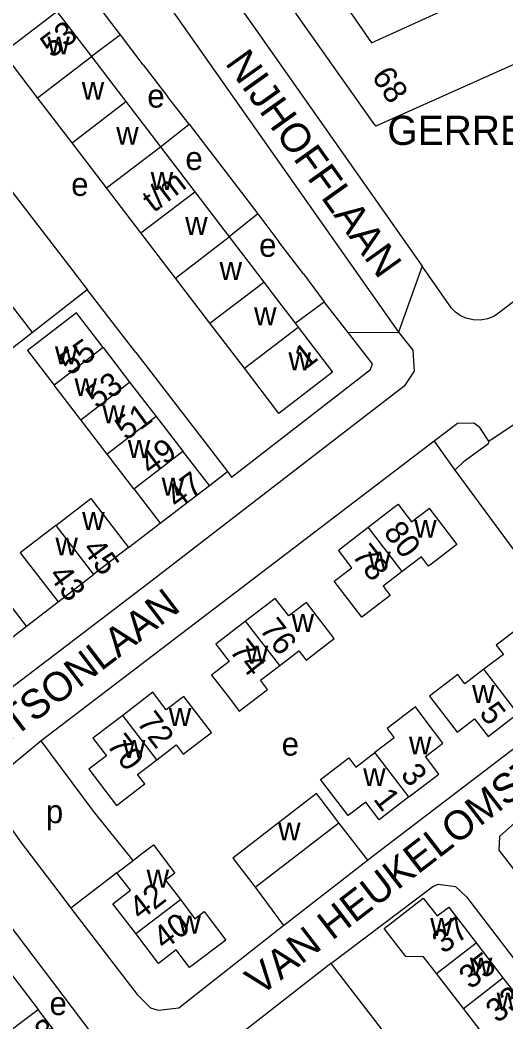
# Model space of a CAD drawing. Extents: x 158848 to 160613, y 385889 to 387762.
# Drawn here: x 160197.3 to 160280.6, y 386662.2 to 386833.8 of the extents above; entities that cross this region are included whole.
import ezdxf

# ---------------------------------------------------------------- set-up
doc = ezdxf.new("R2010")
doc.units = 0
for name, color, linetype in [('BLT_Basislijn', 7, 'Continuous'), ('BLT_Bebouwing', 7, 'Continuous'), ('BLT_Centroide', 7, 'Continuous'), ('BLT_Huisnummer', 7, 'Continuous'), ('BLT_Huisnummer_ tussenligend', 7, 'Continuous'), ('BLT_Huisnummer_reeks', 7, 'Continuous'), ('BLT_Onderverdeling_panden', 7, 'Continuous'), ('BLT_Straatnaam', 7, 'Continuous'), ('BLT_Vlakafsluiter', 7, 'Continuous')]:
    doc.layers.add(name, color=color, linetype=linetype)

msp = doc.modelspace()

# ---------------------------------------------------------------- linework, layer by layer
at = {"layer": 'BLT_Basislijn'}
for p, q in [((160214.52, 386831.26), (160210.62, 386836.33)), ((160214.52, 386831.26), (160209.53, 386827.53)), ((160218.39, 386826.08), (160214.52, 386831.26)), ((160218.39, 386826.08), (160222.58, 386820.68)), ((160226.29, 386815.94), (160222.58, 386820.68)), ((160221.34, 386812.08), (160226.29, 386815.94)), ((160226.29, 386815.94), (160238.04, 386800.58)), ((160238.04, 386800.58), (160233.15, 386796.63)), ((160238.04, 386800.58), (160241.64, 386795.77)), ((160245.86, 386790.28), (160241.64, 386795.77)), ((160245.86, 386790.28), (160249.43, 386785.51)), ((160199.36, 386780.27), (160208.81, 386787.6)), ((160217.12, 386776.82), (160208.81, 386787.6)), ((160195, 386785.9), (160199.36, 386780.27)), ((160244.45, 386781.85), (160249.43, 386785.51)), ((160253.56, 386780.23), (160249.43, 386785.51)), ((160188.56, 386771.9), (160199.36, 386780.27)), ((160268.26, 386761.65), (160200.94, 386710.29)), ((160268.26, 386761.65), (160271.82, 386756.68)), ((160229.74, 386754.03), (160232.84, 386756.43)), ((160271.82, 386756.68), (160294.41, 386725.95)), ((160215.91, 386743.44), (160221.3, 386747.61)), ((160198.42, 386729.93), (160203.82, 386734.15)), ((160256.88, 386689.9), (160251.95, 386696.29)), ((160188.23, 386688.31), (160218.11, 386648.95)), ((160213.91, 386687.72), (160206.02, 386681.65)), ((160237.59, 386685.24), (160242.45, 386678.66)), ((160191.71, 386675.65), (160200.38, 386664.32)), ((160250.58, 386672.17), (160304.3, 386602.61))]:
    msp.add_line(p, q, dxfattribs=at)
for points in [[(160222.17, 386854.05), (160237.27, 386832.78), (160266.19, 386791.63)], [(160209.22, 386848.6), (160210.11, 386849.02), (160211.97, 386849.29), (160213.28, 386848.98), (160214.47, 386848.13), (160262.15, 386780.3)], [(160179.24, 386825.93), (160205.57, 386791.81)], [(160290.48, 386794.11), (160288.29, 386791.23), (160286.43, 386789.22), (160284.64, 386787.62), (160279.32, 386783.55), (160278.5, 386783.02), (160277.43, 386782.58), (160276.23, 386782.36), (160274.94, 386782.4), (160273.73, 386782.71), (160272.75, 386783.14), (160271.94, 386783.74), (160271.25, 386784.44), (160266.19, 386791.63)], [(160205.57, 386791.81), (160208.81, 386787.6)], [(160262.15, 386780.3), (160264.62, 386777.22), (160264.84, 386773.63), (160263.16, 386771.08), (160219.2, 386737.19), (160136.62, 386674.36), (160133.98, 386672.88), (160132.87, 386672.77), (160131.28, 386673.09), (160129.35, 386675.17), (160128.56, 386676.18)], [(160232.84, 386756.43), (160233.56, 386755.48), (160257.38, 386773.93), (160257.68, 386774.9), (160253.56, 386780.23)], [(160253.56, 386780.23), (160262.15, 386780.3)], [(160217.12, 386776.82), (160232.84, 386756.43)], [(160277.67, 386761.63), (160276.11, 386763.97), (160275.1, 386764.74), (160272.26, 386764.66), (160268.26, 386761.65)], [(160271.82, 386756.68), (160273.49, 386758.29), (160277.58, 386761.27), (160277.67, 386761.63)], [(160297.47, 386721.3), (160287.96, 386713.58), (160256.88, 386689.9)], [(160319.16, 386701), (160310.98, 386712.3), (160308.27, 386714.83), (160305.15, 386714.7), (160285.31, 386699.15), (160279.48, 386693.93), (160279.36, 386691.57), (160288.87, 386679.32)], [(160200.94, 386710.29), (160193.73, 386704.4), (160192.73, 386702.17), (160192.97, 386699.26)], [(160216.66, 386689.84), (160209.88, 386698.25), (160200.94, 386710.29)], [(160192.97, 386699.26), (160197.35, 386693), (160204.67, 386683.42), (160206.02, 386681.65)], [(160242.45, 386678.66), (160256.58, 386689.67), (160256.88, 386689.9)], [(160250.58, 386672.17), (160268.02, 386685.39), (160268.98, 386685.74), (160271.92, 386685.34), (160273.79, 386683.57), (160325.19, 386616.52), (160325.69, 386615.85)], [(160206.02, 386681.65), (160217.34, 386666.87), (160219.66, 386664.61), (160220.94, 386664.18), (160224.53, 386664.56), (160241.5, 386677.92), (160242.45, 386678.66)], [(160250.58, 386672.17), (160230.2, 386656.33), (160228.95, 386654.25), (160229.21, 386651.93), (160280.78, 386584.48)]]:
    msp.add_lwpolyline(points, dxfattribs=at)
at = {"layer": 'BLT_Bebouwing'}
for p, q in [((160209.53, 386827.53), (160213.38, 386822.49)), ((160213.38, 386822.49), (160215.43, 386819.8)), ((160206.21, 386812.75), (160200.31, 386820.47)), ((160215.43, 386819.8), (160217.65, 386816.9)), ((160217.65, 386816.9), (160221.34, 386812.08)), ((160212.12, 386805.03), (160206.21, 386812.75)), ((160221.34, 386812.08), (160227.25, 386804.35)), ((160218.02, 386797.3), (160212.12, 386805.03)), ((160227.25, 386804.35), (160233.15, 386796.63)), ((160223.93, 386789.58), (160218.02, 386797.3)), ((160233.15, 386796.63), (160236.89, 386791.75)), ((160236.89, 386791.75), (160239.06, 386788.9)), ((160229.84, 386781.85), (160223.93, 386789.58)), ((160239.06, 386788.9), (160241.03, 386786.32)), ((160241.03, 386786.32), (160244.45, 386781.85)), ((160235.74, 386774.13), (160229.84, 386781.85)), ((160244.45, 386781.85), (160244.96, 386781.18)), ((160211.52, 386777.68), (160216.07, 386771.77)), ((160207.7, 386765.32), (160203.15, 386771.24)), ((160216.07, 386771.77), (160220.63, 386765.85)), ((160212.24, 386759.4), (160207.7, 386765.32)), ((160220.63, 386765.85), (160225.18, 386759.94)), ((160216.79, 386753.48), (160212.24, 386759.4)), ((160237.59, 386685.24), (160251.95, 386696.29)), ((160213.91, 386687.72), (160216.66, 386689.84)), ((160275.46, 386675.7), (160280.07, 386669.72)), ((160273.28, 386664.49), (160268.68, 386670.47)), ((160280.07, 386669.72), (160284.67, 386663.74)), ((160205.04, 386658.26), (160200.38, 386664.32)), ((160277.88, 386658.52), (160273.28, 386664.49))]:
    msp.add_line(p, q, dxfattribs=at)
msp.add_lwpolyline([(160244.56, 386848.67), (160257.55, 386829.86), (160300.86, 386849.59), (160291.65, 386861.46)], close=True, dxfattribs=at)
for points in [[(160309.97, 386840.55), (160298.85, 386835.59), (160301.29, 386833.31), (160286.63, 386826.7), (160285.77, 386827.9), (160258.27, 386815.6), (160257.37, 386816.84), (160238.05, 386844.21)], [(160200.31, 386820.47), (160194.4, 386828.2), (160203.62, 386835.25), (160209.53, 386827.53)], [(160211.52, 386777.68), (160206.97, 386783.6), (160198.59, 386777.17), (160203.15, 386771.24)], [(160244.96, 386781.18), (160250.87, 386773.45), (160241.65, 386766.4), (160235.74, 386774.13)], [(160229.74, 386754.03), (160225.18, 386759.94)], [(160216.79, 386753.48), (160221.3, 386747.61)], [(160221.3, 386747.61), (160229.74, 386754.03)], [(160203.42, 386747.18), (160209.45, 386751.81), (160215.91, 386743.44)], [(160256.98, 386746.94), (160260.95, 386750), (160262.08, 386750.87), (160262.74, 386750), (160264.4, 386747.83), (160267.25, 386750), (160267.44, 386750.15), (160267.55, 386750), (160272.17, 386743.97), (160268.2, 386740.93), (160267.32, 386740.26), (160266.11, 386741.85), (160262.81, 386739.33)], [(160203.42, 386747.18), (160197.34, 386742.52), (160203.82, 386734.15)], [(160262.81, 386739.33), (160259.52, 386736.8), (160260.73, 386735.22), (160255.89, 386731.51), (160254.19, 386733.71), (160251.13, 386737.67), (160254.16, 386739.96), (160251.86, 386742.99), (160256.98, 386746.94)], [(160215.91, 386743.44), (160209.87, 386738.79)], [(160203.82, 386734.15), (160209.87, 386738.79)], [(160198.42, 386729.93), (160193.87, 386735.85)], [(160241.8, 386723.21), (160245.09, 386725.73), (160246.31, 386724.15), (160251.14, 386727.85), (160249.43, 386730.07), (160246.38, 386734.03), (160243.36, 386731.73), (160241.04, 386734.72), (160235.96, 386730.83)], [(160235.96, 386730.83), (160230.83, 386726.9), (160233.16, 386723.9), (160230.13, 386721.59), (160233.17, 386717.62), (160234.87, 386715.4), (160239.71, 386719.1), (160238.5, 386720.69), (160241.8, 386723.21)], [(160190.05, 386723.48), (160198.42, 386729.93)], [(160282.64, 386714.98), (160287.75, 386718.89), (160285.49, 386721.89), (160288.47, 386724.22), (160283.76, 386730.41), (160279.79, 386727.38), (160278.91, 386726.71), (160280.13, 386725.12), (160276.81, 386722.59)], [(160276.81, 386722.59), (160273.53, 386720.09), (160272.32, 386721.68), (160267.47, 386717.98), (160269.16, 386715.76), (160272.19, 386711.78), (160275.21, 386714.08), (160277.52, 386711.06), (160282.64, 386714.98)], [(160220.74, 386707.07), (160224.04, 386709.61), (160225.26, 386708.02), (160230.11, 386711.74), (160228.4, 386713.96), (160225.36, 386717.93), (160222.35, 386715.62), (160220.04, 386718.63), (160214.89, 386714.68)], [(160263.95, 386700.7), (160269.06, 386704.6), (160266.77, 386707.61), (160269.77, 386709.93), (160266.74, 386713.91), (160265.05, 386716.12), (160260.21, 386712.42), (160261.42, 386710.84), (160258.13, 386708.32)], [(160214.89, 386714.68), (160209.79, 386710.77), (160212.1, 386707.77), (160209.1, 386705.45), (160213.83, 386699.23), (160217.79, 386702.28), (160218.67, 386702.95), (160217.45, 386704.54), (160220.74, 386707.07)], [(160253.54, 386697.51), (160250.49, 386701.48), (160248.79, 386703.7), (160253.63, 386707.4), (160254.84, 386705.81), (160258.13, 386708.32)], [(160251.95, 386696.29), (160248.9, 386700.25), (160248.11, 386701.28), (160233.75, 386690.24), (160234.54, 386689.21), (160237.59, 386685.24)], [(160263.95, 386700.7), (160258.85, 386696.8), (160256.55, 386699.8), (160253.54, 386697.51)], [(160216.66, 386689.84), (160217.88, 386690.77), (160220.15, 386692.52), (160223.84, 386687.67), (160222.25, 386686.46), (160224.77, 386683.15)], [(160217.12, 386677.3), (160213.21, 386682.41), (160216.22, 386684.71), (160213.91, 386687.72)], [(160224.77, 386683.15), (160227.28, 386679.85), (160228.87, 386681.06), (160229.54, 386680.18), (160232.56, 386676.2), (160226.36, 386671.48), (160224.06, 386674.49), (160221.04, 386672.19), (160217.12, 386677.3)], [(160268.68, 386670.47), (160266.47, 386673.33), (160263.44, 386673.35), (160259.7, 386678.18), (160266.39, 386683.37), (160268.79, 386680.32), (160270.77, 386681.8), (160275.46, 386675.7)], [(160198.22, 386653.02), (160193.56, 386659.08), (160196.97, 386661.7), (160200.38, 386664.32)]]:
    msp.add_lwpolyline(points, dxfattribs=at)
at = {"layer": 'BLT_Onderverdeling_panden'}
for p, q in [((160200.31, 386820.47), (160209.53, 386827.53)), ((160206.21, 386812.75), (160215.43, 386819.8)), ((160212.12, 386805.03), (160221.34, 386812.08)), ((160218.02, 386797.3), (160227.25, 386804.35)), ((160223.93, 386789.58), (160233.15, 386796.63)), ((160229.84, 386781.85), (160239.06, 386788.9)), ((160235.74, 386774.13), (160244.96, 386781.18)), ((160211.52, 386777.68), (160203.15, 386771.24)), ((160207.7, 386765.32), (160216.07, 386771.77)), ((160220.63, 386765.85), (160212.24, 386759.4)), ((160216.79, 386753.48), (160225.18, 386759.94)), ((160203.42, 386747.18), (160209.87, 386738.79)), ((160262.81, 386739.33), (160256.98, 386746.94)), ((160241.8, 386723.21), (160235.96, 386730.83)), ((160282.64, 386714.98), (160276.81, 386722.59)), ((160220.74, 386707.07), (160214.89, 386714.68)), ((160263.95, 386700.7), (160258.13, 386708.32)), ((160217.12, 386677.3), (160224.77, 386683.15)), ((160268.68, 386670.47), (160275.46, 386675.7)), ((160273.28, 386664.49), (160280.07, 386669.72))]:
    msp.add_line(p, q, dxfattribs=at)
at = {"layer": 'BLT_Vlakafsluiter'}
for p, q in [((160266.19, 386791.63), (160262.15, 386780.3)), ((160277.67, 386761.63), (160284.41, 386766.17))]:
    msp.add_line(p, q, dxfattribs=at)

# ---------------------------------------------------------------- texts
at = {"layer": 'BLT_Centroide'}
for s, p in [('w', (160201.96, 386827.88)), ('w', (160207.87, 386820.12)), ('e', (160219.11, 386818.78)), ('w', (160213.77, 386812.41)), ('e', (160225.63, 386808.09)), ('e', (160206.06, 386803.65)), ('w', (160219.68, 386804.69)), ('w', (160225.59, 386796.97)), ('e', (160238.27, 386793.23)), ('w', (160231.49, 386789.25)), ('w', (160237.4, 386781.5)), ('w', (160203.28, 386774.8)), ('w', (160243.3, 386773.78)), ('w', (160206.62, 386769.36)), ('w', (160211.41, 386764.71)), ('w', (160215.76, 386758.76)), ('w', (160221.57, 386752.3)), ('w', (160207.93, 386746.42)), ('w', (160264.84, 386745.09)), ('w', (160203.35, 386742.07)), ('w', (160256.97, 386739.64)), ('w', (160243.84, 386728.97)), ('w', (160235.97, 386723.53)), ('w', (160274.78, 386716.81)), ('w', (160222.78, 386712.84)), ('w', (160214.92, 386707.36)), ('e', (160242.13, 386707.78)), ('w', (160263.95, 386707.98)), ('w', (160256.1, 386702.56)), ('p', (160201.71, 386696.21)), ('w', (160241.52, 386693.25)), ('w', (160218.98, 386685.17)), ('w', (160224.43, 386677.31)), ('w', (160267.59, 386676.91)), ('w', (160274.38, 386670.09)), ('w', (160278.97, 386664.12)), ('e', (160202.34, 386663.34))]:
    msp.add_text(s, height=4, dxfattribs=at).set_placement(p)
at = {"layer": 'BLT_Huisnummer'}
for s, rotation, p in [('55', 36.2399, (160205.85, 386772.75)), ('51', 36.2399, (160215.45, 386761.66)), ('47', 36.2399, (160224.21, 386749.95)), ('80', 307.4232, (160259.46, 386746.01)), ('45', 306.2399, (160207.84, 386743.13)), ('78', 307.8049, (160254.04, 386742.06)), ('43', 306.2399, (160202.06, 386738.65)), ('76', 307.8049, (160238.19, 386729.39)), ('74', 307.8049, (160233.05, 386725.75)), ('5', 307.4589, (160275.86, 386715.04)), ('72', 307.2204, (160217.16, 386713.44)), ('70', 307.2204, (160212.01, 386709.6)), ('3', 307.4589, (160262.37, 386704.54)), ('1', 307.4589, (160257.72, 386700.33)), ('42', 37.4496, (160217.92, 386679.43)), ('40', 37.2508, (160222.02, 386674.38)), ('37', 37.5758, (160269.88, 386673.7)), ('33', 37.5758, (160279.09, 386661.85)), ('23', 37.5442, (160199.42, 386656.36))]:
    msp.add_text(s, height=4, rotation=rotation, dxfattribs=at).set_placement(p)
at = {"layer": 'BLT_Huisnummer_ tussenligend'}
for s, rotation, p in [('53', 36.2399, (160210.45, 386767.06)), ('49', 36.2399, (160219.66, 386755.68)), ('35', 37.5758, (160274.49, 386667.63))]:
    msp.add_text(s, height=4, rotation=rotation, dxfattribs=at).set_placement(p)
at = {"layer": 'BLT_Huisnummer_reeks'}
for s, rotation, p in [('53', 37.404, (160202.73, 386827.14)), ('68', 303.5058, (160257.44, 386824.12)), ('t/m', 37.404, (160220.19, 386800.67)), ('1', 37.3971, (160246.25, 386773.87))]:
    msp.add_text(s, height=4, rotation=rotation, dxfattribs=at).set_placement(p)
at = {"layer": 'BLT_Straatnaam'}
for s, rotation, p in [('NIJHOFFLAAN', 305.5979, (160232.33, 386826.37)), ('GERRETSONLAAN', 37.3419, (160177.5, 386696.47)), ('VAN HEUKELOMSTRAAT', 37.6482, (160238.42, 386666.49))]:
    msp.add_text(s, height=5, rotation=rotation, dxfattribs=at).set_placement(p)
msp.add_text('GERRETSONPLEIN', height=5, dxfattribs=at).set_placement((160260.24, 386812.38))

doc.saveas('drawing.dxf')
